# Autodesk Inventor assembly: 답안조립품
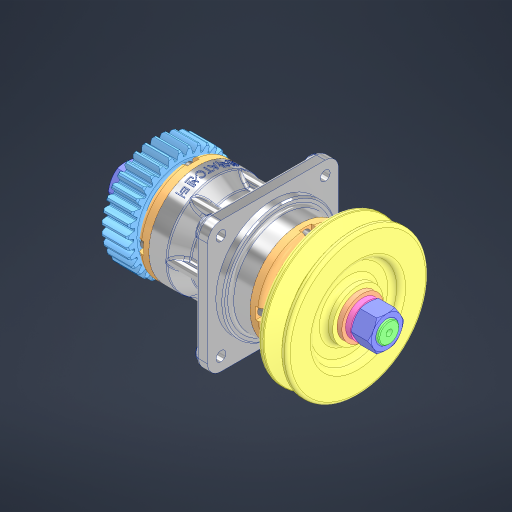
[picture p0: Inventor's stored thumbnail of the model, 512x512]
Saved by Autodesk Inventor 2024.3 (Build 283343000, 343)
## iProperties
Created: 2025-08
Part Number: 답안조립품
Document SubType Name: Assembly
Designer: user
Author: user
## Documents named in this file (14)
- C:\Users\user\Desktop\750803V1005\답안조립품.iam
- C:\Users\user\Desktop\750803V1005\1-본체.ipt
- C:\Users\user\Desktop\750803V1005\깊은 홈 볼 베어링 6005\깊은 홈 볼 베어링 6005\깊은 홈 볼 베어링 6005.ipt
- C:\Users\user\Desktop\750803V1005\축\축\축.ipt
- C:\Users\user\Desktop\750803V1005\커버\커버\커버.ipt
- C:\Users\user\Desktop\750803V1005\오일 실 25 38 5\오일 실 25 38 5\오일 실 25 38 5.ipt
- C:\Users\user\Desktop\750803V1005\6각 구멍붙이 볼트 M4x10\6각 구멍붙이 볼트 M4x10\6각 구멍붙이 볼트 M4x10.ipt
- C:\Users\user\Desktop\750803V1005\평행 키 6x6x14\평행 키 6x6x14\평행 키 6x6x14.ipt
- C:\Users\user\Desktop\750803V1005\평행 키 6x6x18\평행 키 6x6x18\평행 키 6x6x18.ipt
- C:\Users\user\Desktop\750803V1005\V 벨트 풀리\V 벨트 풀리\V 벨트 풀리.ipt
- C:\Users\user\Desktop\750803V1005\스퍼기어\스퍼기어\스퍼기어.ipt
- C:\Users\user\Desktop\750803V1005\평 와셔 M14\평 와셔 M14\평 와셔 M14.ipt
- C:\Users\user\Desktop\750803V1005\스프링 와셔 M14\스프링 와셔 M14\스프링 와셔 M14.ipt
- C:\Users\user\Desktop\750803V1005\6각 너트 M14x1\6각 너트 M14x1\6각 너트 M14x1.ipt
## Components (12 placed, 4 different names)
1. 1-본체:1
2. 6각 구멍붙이 볼트 M4x10:1 — 각도:6
3. 6각 구멍붙이 볼트 M4x10:2 — 각도:7
4. 6각 구멍붙이 볼트 M4x10:3 — 각도:8
5. 6각 구멍붙이 볼트 M4x10:4 — 각도:5
6. 6각 구멍붙이 볼트 M4x10:5 — 각도:1
7. 6각 구멍붙이 볼트 M4x10:6 — 각도:3
8. 6각 구멍붙이 볼트 M4x10:7 — 각도:4
9. 6각 구멍붙이 볼트 M4x10:8 — 각도:2
10. V 벨트 풀리:1
11. 6각 너트 M14x1:1 — 각도:9
12. 6각 너트 M14x1:2 — 각도:10
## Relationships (10: Angle 10)
- 각도:1 [Angle]: 6각 구멍붙이 볼트 M4x10:5
- 각도:2 [Angle]: 6각 구멍붙이 볼트 M4x10:8
- 각도:3 [Angle]: 6각 구멍붙이 볼트 M4x10:6
- 각도:4 [Angle]: 6각 구멍붙이 볼트 M4x10:7
- 각도:5 [Angle]: 6각 구멍붙이 볼트 M4x10:4
- 각도:6 [Angle]: 6각 구멍붙이 볼트 M4x10:1
- 각도:7 [Angle]: 6각 구멍붙이 볼트 M4x10:2
- 각도:8 [Angle]: 6각 구멍붙이 볼트 M4x10:3
- 각도:9 [Angle]: 6각 너트 M14x1:1
- 각도:10 [Angle]: 6각 너트 M14x1:2
